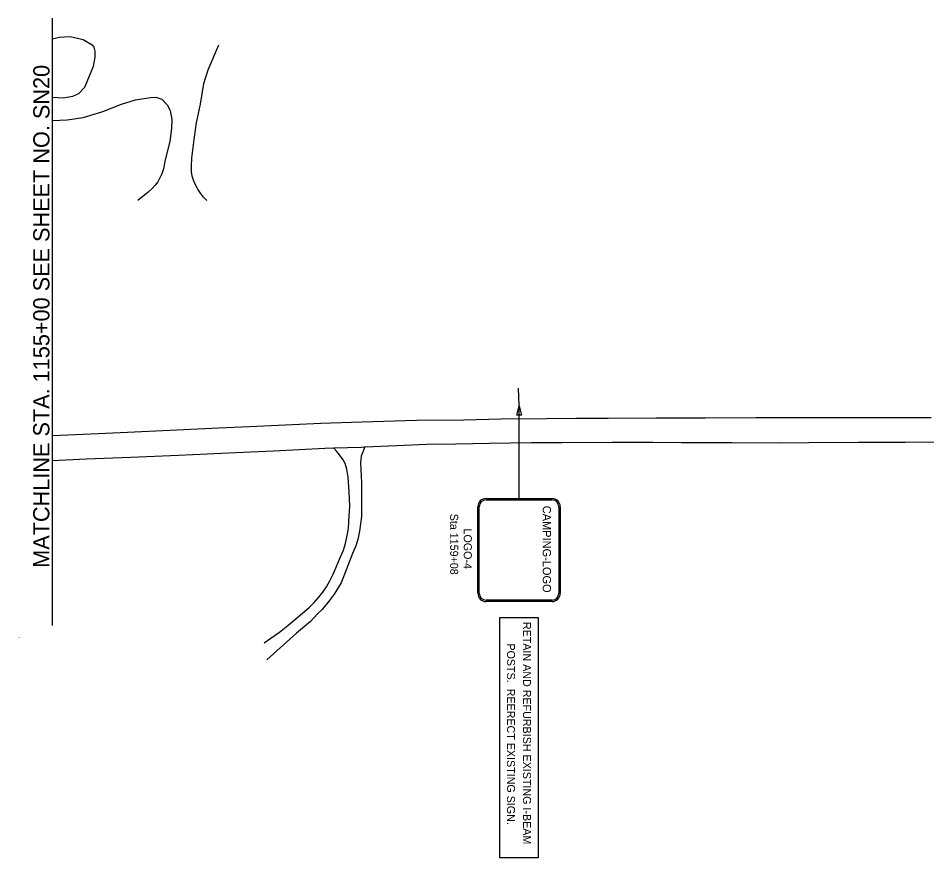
# Model space of a CAD drawing. Extents: x 1738684 to 1740273, y 1165576 to 1166490.
# Drawn here: x 1738684 to 1739479, y 1165576 to 1166310 of the extents above; entities that cross this region are included whole.
import ezdxf

# ---------------------------------------------------------------- set-up
doc = ezdxf.new("R2010")
doc.units = 0
for name, color, linetype in [('Default', 7, 'Continuous'), ('RD_EX_Driveway', 7, 'Continuous'), ('RD_EX_Road', 7, 'Continuous'), ('RD_SHT_MatchLine', 7, 'Continuous'), ('RD_SHT_TX', 7, 'Continuous'), ('SN_P_Signs', 7, 'Continuous')]:
    doc.layers.add(name, color=color, linetype=linetype)

msp = doc.modelspace()

# ---------------------------------------------------------------- linework, layer by layer
at = {"layer": 'RD_EX_Driveway'}
for points in [[(1738713.73, 1166292.08), (1738719.56, 1166293.78), (1738729.1, 1166294.16), (1738740.58, 1166291.72), (1738748.53, 1166287.08), (1738749.87, 1166284.89), (1738750.73, 1166281.46), (1738750.86, 1166276.21), (1738749.39, 1166267.89), (1738741.64, 1166249.53)], [(1738848.86, 1166150.79), (1738845.96, 1166153.76), (1738843.23, 1166157.14), (1738840.81, 1166160.75), (1738840.17, 1166161.83), (1738838.44, 1166165.14), (1738837.07, 1166168.6), (1738836.07, 1166172.19), (1738835.46, 1166175.87), (1738835.25, 1166179.59), (1738835.26, 1166180.92), (1738835.69, 1166187.96), (1738837.7, 1166204.29), (1738839.84, 1166218.72), (1738843.32, 1166235.05), (1738846.18, 1166253.2), (1738849.91, 1166265.17), (1738859.36, 1166286.85)], [(1738741.64, 1166249.53), (1738736.5, 1166244.14), (1738731.36, 1166241.93), (1738723.65, 1166240.34), (1738713.86, 1166240.94), (1738713.73, 1166240.99)], [(1738713.73, 1166220.9), (1738726.72, 1166221.33), (1738740.55, 1166223.55), (1738750.22, 1166226.25), (1738757.69, 1166228.7), (1738765.89, 1166232.02), (1738774.22, 1166234.96), (1738786.34, 1166238.77), (1738799.44, 1166240.99), (1738804.1, 1166241.11), (1738809.36, 1166239.53), (1738814.13, 1166234.63), (1738816.7, 1166229.5), (1738818.17, 1166221.55), (1738817.93, 1166213.72), (1738816.47, 1166202.58), (1738811.95, 1166185.33), (1738811.48, 1166181.51), (1738810.62, 1166177.76), (1738809.38, 1166174.12), (1738807.77, 1166170.62), (1738805.82, 1166167.31), (1738803.53, 1166164.22), (1738800.94, 1166161.37), (1738798.08, 1166158.81), (1738797.39, 1166158.27), (1738788.54, 1166150.79)], [(1738898.79, 1165764.21), (1738904.71, 1165768.1), (1738912.17, 1165773.29), (1738919.51, 1165779.28), (1738934.06, 1165791.44), (1738938.49, 1165795.23), (1738942.65, 1165799.32), (1738946.52, 1165803.68), (1738950.09, 1165808.28), (1738953.34, 1165813.12), (1738956.25, 1165818.17), (1738958.82, 1165823.41), (1738959.18, 1165824.21), (1738966.09, 1165839.77), (1738968.21, 1165845.23), (1738969.95, 1165850.82), (1738971.32, 1165856.52), (1738972.3, 1165862.3), (1738972.89, 1165868.13), (1738973.01, 1165870.33), (1738973.78, 1165883.62), (1738973.33, 1165896.04), (1738972.25, 1165909.07), (1738971.34, 1165916.07), (1738969.84, 1165920.85), (1738967.97, 1165924.04), (1738964.75, 1165928.44), (1738962.39, 1165931.25), (1738959.55, 1165934.54)], [(1738986.9, 1165935.43), (1738983.69, 1165927.23), (1738983.24, 1165921.33), (1738984.09, 1165903.87), (1738983.94, 1165890.46), (1738983.93, 1165874.59), (1738982.17, 1165861.66), (1738980.74, 1165854.39), (1738979.06, 1165848.96), (1738976.28, 1165842.05), (1738973.37, 1165834.64), (1738971.32, 1165829.22), (1738966.36, 1165816.63), (1738960.03, 1165806.74), (1738955.76, 1165800.93), (1738949.54, 1165793.26), (1738945.51, 1165789.3), (1738939.41, 1165782.86), (1738927.15, 1165772.62), (1738901.2, 1165749.29)]]:
    msp.add_lwpolyline(points, dxfattribs=at)
at = {"layer": 'RD_EX_Road'}
for points in [[(1738713.73, 1165945.43), (1738747.43, 1165946.95), (1738779.36, 1165948.33), (1738816.52, 1165950.15), (1738859.28, 1165952.09), (1738892.53, 1165953.41), (1738948.59, 1165956.03), (1738984.19, 1165957.18), (1739032.27, 1165958.79), (1739073.43, 1165958.94), (1739106.13, 1165959.83), (1739145.87, 1165960.15), (1739172.1, 1165960.38), (1739199.74, 1165960.5), (1739241.67, 1165960.72), (1739259.41, 1165960.87), (1739284.68, 1165960.81), (1739329.01, 1165961.01), (1739391.23, 1165961.04), (1739438.73, 1165961.23), (1739482.2, 1165961.17)], [(1738713.73, 1165923.58), (1738743.1, 1165925.03), (1738782.3, 1165926.36), (1738824.09, 1165928.3), (1738874.19, 1165930.62), (1738907.09, 1165932.06), (1738952.01, 1165934.31), (1738959.55, 1165934.54), (1738984, 1165935.31), (1738986.9, 1165935.43), (1739014.63, 1165936.56), (1739041.22, 1165937.66), (1739066.56, 1165937.95), (1739095.56, 1165938.63), (1739132.83, 1165939.19), (1739159.7, 1165939.18), (1739203.46, 1165939.53), (1739238.98, 1165939.57), (1739263.94, 1165939.29), (1739308.32, 1165939.31), (1739349.24, 1165939.09), (1739375.25, 1165939.22), (1739418.79, 1165939.41), (1739459.48, 1165939.5), (1739504.95, 1165939.79)]]:
    msp.add_lwpolyline(points, dxfattribs=at)
at = {"layer": 'RD_SHT_MatchLine'}
msp.add_lwpolyline([(1738713.73, 1165779.26), (1738713.73, 1166044.04), (1738713.73, 1166310.27)], dxfattribs=at)
at = {"layer": 'SN_P_Signs'}
for p, q in [((1739121.87, 1165971.43), (1739121.4, 1165986.61)), ((1739121.87, 1165890.21), (1739121.87, 1165971.43)), ((1739105.06, 1165576.09), (1739105.06, 1165786.11)), ((1739105.06, 1165786.11), (1739138.68, 1165786.11)), ((1739138.68, 1165786.11), (1739138.68, 1165576.09)), ((1739138.68, 1165576.09), (1739105.06, 1165576.09))]:
    msp.add_line(p, q, dxfattribs=at)
msp.add_lwpolyline([(1739119.82, 1165963.23), (1739121.87, 1165971.43), (1739123.92, 1165963.23)], close=True, dxfattribs=at)
for points in [[(1739093.07, 1165890.21), (1739150.67, 1165890.21)], [(1739093.07, 1165889.01), (1739150.67, 1165889.01)], [(1739085.87, 1165807.41), (1739085.87, 1165883.01)], [(1739087.07, 1165807.41), (1739087.07, 1165883.01)], [(1739156.67, 1165883.01), (1739156.67, 1165807.41)], [(1739157.87, 1165883.01), (1739157.87, 1165807.41)], [(1739150.67, 1165801.41), (1739093.07, 1165801.41)], [(1739150.67, 1165800.21), (1739093.07, 1165800.21)]]:
    msp.add_lwpolyline(points, dxfattribs=at)
for centre, radius, start, end in [((1739093.07, 1165883.01), 7.2, 90, 180), ((1739093.07, 1165883.01), 6, 90, 180), ((1739150.67, 1165883.01), 7.2, 0, 90), ((1739150.67, 1165883.01), 6, 0, 90), ((1739093.07, 1165807.41), 7.2, 180, 270), ((1739093.07, 1165807.41), 6, 180, 270), ((1739150.67, 1165807.41), 6, 270, 0), ((1739150.67, 1165807.41), 7.2, 270, 0)]:
    msp.add_arc(centre, radius, start, end, dxfattribs=at)

# ---------------------------------------------------------------- texts
at = {"layer": 'Default'}
for s, height, p in [('Angle:  35.6135', 0.2083, (1738683.73, 1165768.56)), ('Align: A_I85', 0.2083, (1738683.73, 1165768.29)), ('Sheet: 21', 0.208, (1738683.73, 1165768.83))]:
    msp.add_text(s, height=height, dxfattribs=at).set_placement(p)
at = {"layer": 'RD_SHT_TX'}
msp.add_text('MATCHLINE STA. 1155+00 SEE SHEET NO. SN20', height=14.1726, rotation=89.98556, dxfattribs=at).set_placement((1738711.02, 1165829.69))
at = {"layer": 'SN_P_Signs'}
for s, height, rotation, p in [('CAMPING-LOGO', 7.2, 270, (1739142.57, 1165883.95)), ('Sta 1159+08', 7, 270.00008, (1739061.6, 1165876.97)), ('LOGO-4', 7, 270.00008, (1739073.5, 1165864.02)), ('RETAIN AND REFURBISH EXISTING I-BEAM', 6.9998, 270.00008, (1739125.31, 1165782.36)), ('POSTS.  REERECT EXISTING SIGN.', 6.9998, 270.00008, (1739111.31, 1165763.55))]:
    msp.add_text(s, height=height, rotation=rotation, dxfattribs=at).set_placement(p)

doc.saveas('drawing.dxf')
